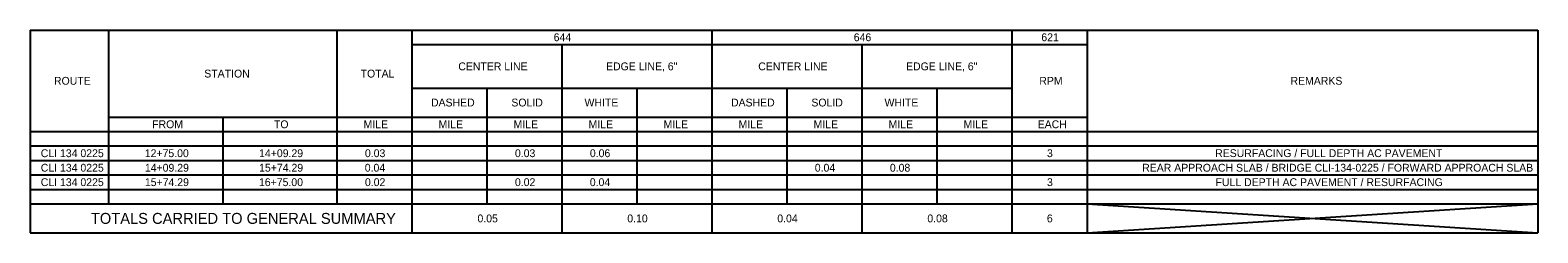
# Model space of a CAD drawing. Extents: x -27.3 to 69.3, y 0 to 30.
# Drawn here: x -27.29 to -0.39, y 26.39 to 30.01 of the extents above; entities that cross this region are included whole.
import ezdxf

# ---------------------------------------------------------------- set-up
doc = ezdxf.new("R2010")
doc.units = 0
doc.layers.add('Default', color=7, linetype='Continuous')

msp = doc.modelspace()

# ---------------------------------------------------------------- linework, layer by layer
at = {"layer": 'Default'}
for p, q in [((-27.295, 30.006), (-0.388, 30.006)), ((-27.295, 30.006), (-27.295, 26.386)), ((-25.895, 30.006), (-25.895, 26.903)), ((-21.819, 30.006), (-21.819, 26.903)), ((-20.481, 30.006), (-20.481, 26.386)), ((-15.127, 30.006), (-15.127, 26.386)), ((-9.773, 30.006), (-9.773, 26.386)), ((-8.434, 30.006), (-8.434, 26.386)), ((-0.388, 30.006), (-0.388, 26.386)), ((-20.481, 29.747), (-8.434, 29.747)), ((-17.804, 29.747), (-17.804, 26.386)), ((-12.45, 29.747), (-12.45, 26.386)), ((-20.481, 28.971), (-9.773, 28.971)), ((-19.142, 28.971), (-19.142, 26.903)), ((-16.465, 28.971), (-16.465, 26.903)), ((-13.788, 28.971), (-13.788, 26.903)), ((-11.111, 28.971), (-11.111, 26.903)), ((-25.895, 28.454), (-8.434, 28.454)), ((-23.857, 28.454), (-23.857, 26.903)), ((-27.295, 28.196), (-8.434, 28.196)), ((-8.434, 28.196), (-0.388, 28.196)), ((-27.295, 27.937), (-0.388, 27.937)), ((-27.295, 27.679), (-0.388, 27.679)), ((-27.295, 27.42), (-0.388, 27.42)), ((-27.295, 27.162), (-0.388, 27.162)), ((-27.295, 26.903), (-0.388, 26.903)), ((-8.434, 26.386), (-0.388, 26.903)), ((-8.434, 26.903), (-0.388, 26.386)), ((-27.295, 26.386), (-0.388, 26.386))]:
    msp.add_line(p, q, dxfattribs=at)

# ---------------------------------------------------------------- texts
for s, height, p in [('644', 0.1399, (-17.952, 29.808)), ('646', 0.1399, (-12.597, 29.808)), ('621', 0.1399, (-9.249, 29.808)), ('CENTER LINE', 0.13993, (-19.654, 29.289)), ('EDGE LINE, 6"', 0.13993, (-17.017, 29.289)), ('CENTER LINE', 0.13993, (-14.301, 29.289)), ('EDGE LINE, 6"', 0.13993, (-11.663, 29.289)), ('ROUTE', 0.1399, (-26.869, 29.031)), ('STATION', 0.1399, (-24.187, 29.16)), ('TOTAL', 0.1399, (-21.397, 29.16)), ('RPM', 0.1399, (-9.285, 29.031)), ('REMARKS', 0.1399, (-4.802, 29.031)), ('DASHED', 0.1399, (-20.141, 28.643)), ('SOLID', 0.1399, (-18.707, 28.643)), ('WHITE', 0.1399, (-17.401, 28.643)), ('DASHED', 0.1399, (-14.787, 28.643)), ('SOLID', 0.1399, (-13.353, 28.643)), ('WHITE', 0.1399, (-12.047, 28.643)), ('FROM', 0.1399, (-25.117, 28.255)), ('TO', 0.1399, (-22.944, 28.255)), ('MILE', 0.1399, (-21.345, 28.255)), ('MILE', 0.1399, (-20.006, 28.255)), ('MILE', 0.1399, (-18.668, 28.255)), ('MILE', 0.1399, (-17.329, 28.255)), ('MILE', 0.1399, (-15.991, 28.255)), ('MILE', 0.1399, (-14.652, 28.255)), ('MILE', 0.1399, (-13.314, 28.255)), ('MILE', 0.1399, (-11.975, 28.255)), ('MILE', 0.1399, (-10.637, 28.255)), ('EACH', 0.1399, (-9.314, 28.255)), ('CLI 134 0225', 0.13993, (-27.105, 27.738)), ('12+75.00', 0.1399, (-25.249, 27.738)), ('14+09.29', 0.1399, (-23.209, 27.738)), ('0.03', 0.1399, (-21.32, 27.738)), ('0.03', 0.1399, (-18.643, 27.738)), ('0.06', 0.1399, (-17.306, 27.738)), ('3', 0.14, (-9.148, 27.738)), ('RESURFACING / FULL DEPTH AC PAVEMENT', 0.13993, (-6.147, 27.739)), ('CLI 134 0225', 0.13993, (-27.105, 27.479)), ('14+09.29', 0.1399, (-25.247, 27.479)), ('15+74.29', 0.1399, (-23.209, 27.479)), ('0.04', 0.1399, (-21.323, 27.479)), ('0.04', 0.1399, (-13.292, 27.479)), ('0.08', 0.1399, (-11.952, 27.479)), ('REAR APPROACH SLAB / BRIDGE CLI-134-0225 / FORWARD APPROACH SLAB', 0.13993, (-7.449, 27.479)), ('CLI 134 0225', 0.13993, (-27.105, 27.221)), ('15+74.29', 0.1399, (-25.247, 27.221)), ('16+75.00', 0.1399, (-23.211, 27.221)), ('0.02', 0.1399, (-21.32, 27.221)), ('0.02', 0.1399, (-18.643, 27.221)), ('0.04', 0.1399, (-17.307, 27.221)), ('3', 0.14, (-9.148, 27.221)), ('FULL DEPTH AC PAVEMENT / RESURFACING', 0.13993, (-6.14, 27.221)), ('TOTALS CARRIED TO GENERAL SUMMARY', 0.1959, (-26.211, 26.546)), ('0.05', 0.1399, (-19.312, 26.574)), ('0.10', 0.1399, (-16.638, 26.574)), ('0.04', 0.1399, (-13.961, 26.574)), ('0.08', 0.1399, (-11.283, 26.574)), ('6', 0.14, (-9.15, 26.574))]:
    msp.add_text(s, height=height, dxfattribs=at).set_placement(p)

doc.saveas('drawing.dxf')
